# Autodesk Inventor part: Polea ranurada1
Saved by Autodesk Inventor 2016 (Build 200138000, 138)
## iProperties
Created: 2016-06
Part Number: Polea ranurada1
Material: Steel
Document SubType Name: Modeling
Designer: adm
Mass: 701.241 g
Surface Area: 207.725 cm^2
Volume: 89.33 cm^3
Density: 7.85 g/cm^3
Appearance: Steel
CustomPartVersion: 1
Author: adm
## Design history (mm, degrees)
sketch "Boceto principal"
  geometry: L1 (0, 19.05)-(43.815, 19.05); L2 (43.815, 19.05)-(43.815, 15.804); L3 (43.815, 15.804)-(32.131, 12.232); L4 (32.131, 12.232)-(32.131, 6.818); L5 (32.131, 6.818)-(43.815, 3.246); L6 (43.815, 3.246)-(43.815, 0); L7 (43.815, 0)-(0, 0); L8 (40.64, 14.834)-(40.64, 4.216); L9 (32.131, 9.525)-(40.64, 9.525); L10 (43.815, 15.804)-(43.815, 3.246); L11 (0, -4)-(0, 24) reference; L12 (0, 0)-(0, 19.05)
  constraints: 22 end point, 5 perpendicular, 2 collinear, 2 midpoint, 2 point on line, 1 parallel
  dimensions: "d0" = 10.6172 distance of L8.start L8.end (= da_Bw); "d1" = 34 deg angle of L3 L5 (= da_Alfa); "d2" = 3.175 distance between parallel lines of L2 L8 (= da_c); "d6" = 19.05 distance between parallel lines of L7 L1 (computed from d5, da_ng, da_Sg); "d21" = 81.28 diameter of L8 L11 (= da_Dw); "d25" = 11.684 distance between parallel lines of L4 L10 (= da_Hd); "d27" = 9.525 distance between parallel lines of L7 L9 (= da_Se)
node "Plano de correa"
revolve "Cuerpo" stored, may be unused: angle "d7" = 90 deg
revolve "Para ranuras" stored, may be unused: angle "d15" = 90 deg
fillet "Empalme externo" dims "d8" = 0 (computed from da_r1), "d10" = 0, "da_r1" = 0 [user parameter; used in 1 equation term]
fillet "Empalme interno" dims "d9" = 0 (computed from da_r2), "d11" = 0, "da_r2" = 0 [user parameter; used in 1 equation term]
pattern_linear "Patrón para ranuras" dims "d18" = 15.875 (= da_Sg)
body "Solid1"
other parameters: "d5" = 9.525 (= da_Se), "da_Bw" = 10.6172 [user parameter; used in 1 equation term], "da_Alfa" = 34 deg [user parameter; used in 1 equation term], "da_c" = 3.175 [user parameter; used in 1 equation term], "da_Dw" = 81.28 [user parameter; used in 1 equation term], "da_Hd" = 11.684 [user parameter; used in 1 equation term], "da_Se" = 9.525 [user parameter; used in 2 equation terms], "da_Sg" = 15.875 [user parameter; used in 2 equation terms], "d24" = 0, "d26" = 0
